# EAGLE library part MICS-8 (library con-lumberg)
CONNECTOR
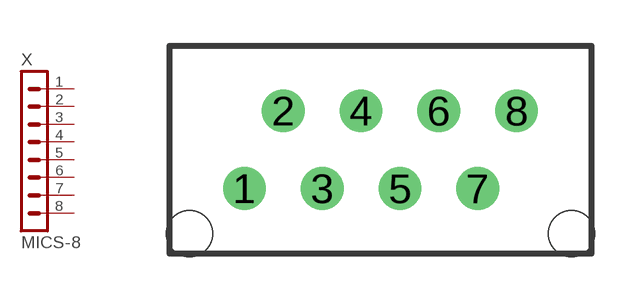
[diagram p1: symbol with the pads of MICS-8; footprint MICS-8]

Designator prefix X

## MICS-8 (OC_FARNELL: unknown; OC_NEWARK: unknown)  [MICS-8]
1  1  pas
2  2  pas
3  3  pas
4  4  pas
5  5  pas
6  6  pas
7  7  pas
8  8  pas

## Footprint MICS-8 (pad centres in mm)
CONNECTOR
drill 0.85 pad 1.397 round: 1 -4.445,-1.27; 2 -3.175,1.27; 3 -1.905,-1.27; 4 -0.635,1.27; 5 0.635,-1.27; 6 1.905,1.27; 7 3.175,-1.27; 8 4.445,1.27
hole 1.5 at 6.245,-2.75
hole 1.5 at -6.245,-2.75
